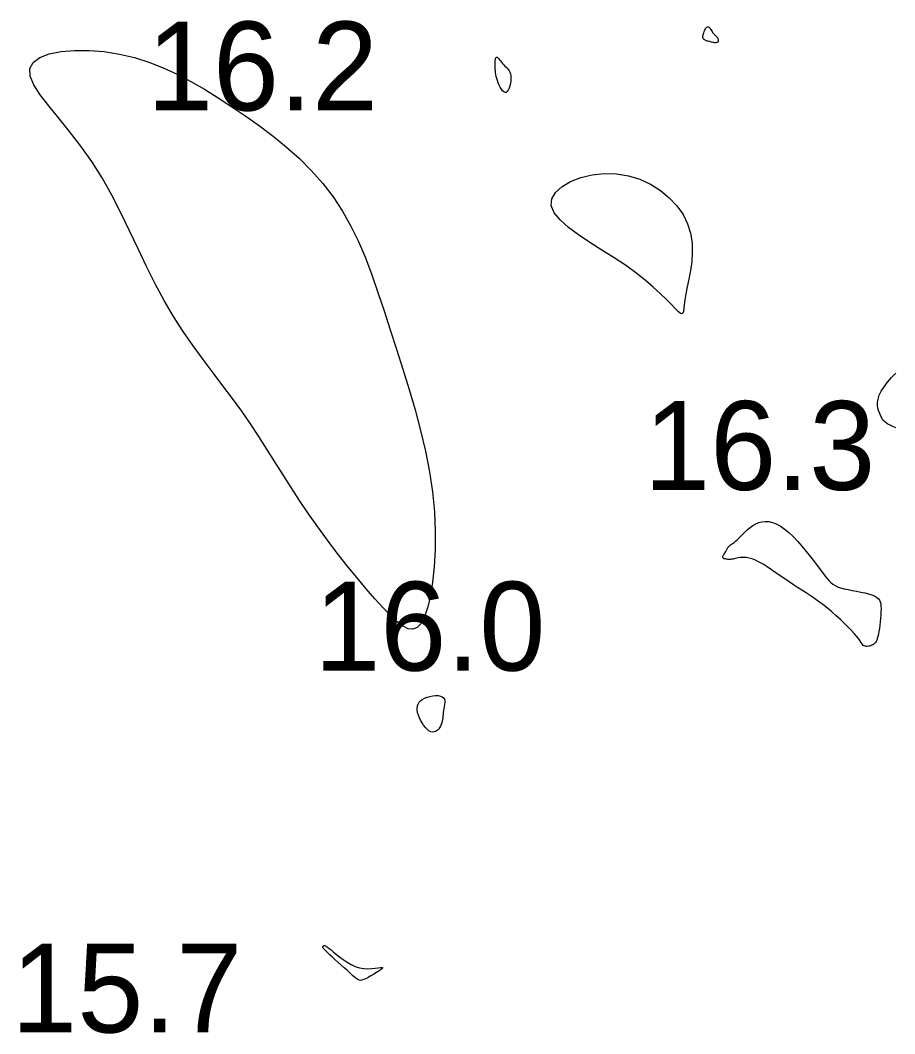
# Model space of a CAD drawing. Extents: x 3040093 to 3056816, y 408076 to 509144.
# Drawn here: x 3045855.6 to 3045904.8, y 434452.5 to 434509.6 of the extents above; entities that cross this region are included whole.
import ezdxf

# ---------------------------------------------------------------- set-up
doc = ezdxf.new("R2010")
doc.units = 0
doc.layers.add('V-CHAN-CONT-EL17', color=7, linetype='Continuous')
doc.layers.add('V-TOPO-SOUN-0610', color=7, linetype='Continuous')

msp = doc.modelspace()

# ---------------------------------------------------------------- linework, layer by layer
at = {"layer": 'V-CHAN-CONT-EL17'}
for points in [[(3045894.628, 434508.794), (3045894.661, 434508.759), (3045894.692, 434508.728), (3045894.723, 434508.701), (3045894.752, 434508.674), (3045894.779, 434508.648), (3045894.804, 434508.619), (3045894.827, 434508.588), (3045894.846, 434508.552), (3045894.861, 434508.514), (3045894.872, 434508.474), (3045894.877, 434508.435), (3045894.875, 434508.398), (3045894.866, 434508.364), (3045894.848, 434508.337), (3045894.821, 434508.316), (3045894.785, 434508.304), (3045894.739, 434508.3), (3045894.687, 434508.302), (3045894.629, 434508.309), (3045894.568, 434508.321), (3045894.504, 434508.335), (3045894.44, 434508.351), (3045894.376, 434508.367), (3045894.315, 434508.382), (3045894.257, 434508.397), (3045894.204, 434508.414), (3045894.155, 434508.433), (3045894.113, 434508.454), (3045894.076, 434508.48), (3045894.048, 434508.51), (3045894.027, 434508.547), (3045894.015, 434508.59), (3045894.011, 434508.639), (3045894.014, 434508.692), (3045894.024, 434508.749), (3045894.038, 434508.807), (3045894.057, 434508.866), (3045894.079, 434508.923), (3045894.103, 434508.979), (3045894.128, 434509.032), (3045894.154, 434509.079), (3045894.182, 434509.121), (3045894.21, 434509.155), (3045894.24, 434509.18), (3045894.27, 434509.195), (3045894.301, 434509.199), (3045894.332, 434509.19), (3045894.364, 434509.167), (3045894.396, 434509.133), (3045894.429, 434509.089), (3045894.462, 434509.04), (3045894.495, 434508.987), (3045894.528, 434508.933), (3045894.561, 434508.882), (3045894.595, 434508.834)], [(3045871.311, 434482.528), (3045870.836, 434483.26), (3045870.375, 434483.986), (3045869.922, 434484.707), (3045869.47, 434485.424), (3045869.012, 434486.137), (3045868.539, 434486.849), (3045868.047, 434487.56), (3045867.528, 434488.271), (3045866.989, 434488.989), (3045866.435, 434489.72), (3045865.873, 434490.47), (3045865.311, 434491.246), (3045864.754, 434492.053), (3045864.209, 434492.899), (3045863.684, 434493.79), (3045863.182, 434494.728), (3045862.696, 434495.705), (3045862.218, 434496.706), (3045861.738, 434497.719), (3045861.247, 434498.729), (3045860.735, 434499.725), (3045860.195, 434500.691), (3045859.616, 434501.616), (3045858.996, 434502.487), (3045858.362, 434503.301), (3045857.747, 434504.055), (3045857.184, 434504.747), (3045856.706, 434505.375), (3045856.348, 434505.936), (3045856.142, 434506.427), (3045856.121, 434506.848), (3045856.309, 434507.195), (3045856.685, 434507.47), (3045857.218, 434507.674), (3045857.878, 434507.808), (3045858.634, 434507.872), (3045859.455, 434507.869), (3045860.311, 434507.798), (3045861.171, 434507.663), (3045862.01, 434507.463), (3045862.826, 434507.204), (3045863.624, 434506.891), (3045864.408, 434506.529), (3045865.183, 434506.123), (3045865.953, 434505.68), (3045866.723, 434505.202), (3045867.497, 434504.698), (3045868.276, 434504.169), (3045869.055, 434503.614), (3045869.825, 434503.033), (3045870.575, 434502.421), (3045871.298, 434501.776), (3045871.983, 434501.097), (3045872.623, 434500.38), (3045873.207, 434499.623), (3045873.73, 434498.824), (3045874.199, 434497.984), (3045874.622, 434497.104), (3045875.011, 434496.185), (3045875.374, 434495.228), (3045875.722, 434494.235), (3045876.063, 434493.207), (3045876.408, 434492.144), (3045876.764, 434491.05), (3045877.122, 434489.929), (3045877.474, 434488.788), (3045877.81, 434487.634), (3045878.12, 434486.473), (3045878.393, 434485.312), (3045878.62, 434484.156), (3045878.791, 434483.014), (3045878.899, 434481.892), (3045878.948, 434480.806), (3045878.943, 434479.772), (3045878.891, 434478.808), (3045878.798, 434477.93), (3045878.671, 434477.154), (3045878.515, 434476.498), (3045878.338, 434475.978), (3045878.144, 434475.607), (3045877.93, 434475.379), (3045877.692, 434475.285), (3045877.427, 434475.315), (3045877.131, 434475.459), (3045876.799, 434475.709), (3045876.428, 434476.054), (3045876.013, 434476.484), (3045875.553, 434476.991), (3045875.055, 434477.564), (3045874.529, 434478.192), (3045873.984, 434478.864), (3045873.43, 434479.57), (3045872.877, 434480.3), (3045872.333, 434481.043), (3045871.809, 434481.789)], [(3045882.408, 434506.287), (3045882.379, 434506.402), (3045882.356, 434506.511), (3045882.34, 434506.616), (3045882.328, 434506.718), (3045882.321, 434506.816), (3045882.318, 434506.912), (3045882.316, 434507.007), (3045882.316, 434507.101), (3045882.317, 434507.19), (3045882.321, 434507.273), (3045882.328, 434507.347), (3045882.339, 434507.409), (3045882.354, 434507.457), (3045882.375, 434507.486), (3045882.401, 434507.495), (3045882.434, 434507.482), (3045882.473, 434507.45), (3045882.517, 434507.401), (3045882.566, 434507.341), (3045882.619, 434507.272), (3045882.676, 434507.198), (3045882.737, 434507.124), (3045882.8, 434507.052), (3045882.865, 434506.986), (3045882.93, 434506.923), (3045882.992, 434506.86), (3045883.051, 434506.793), (3045883.103, 434506.72), (3045883.147, 434506.637), (3045883.18, 434506.542), (3045883.2, 434506.43), (3045883.205, 434506.3), (3045883.198, 434506.158), (3045883.177, 434506.013), (3045883.146, 434505.872), (3045883.106, 434505.743), (3045883.057, 434505.634), (3045883.002, 434505.552), (3045882.941, 434505.507), (3045882.876, 434505.502), (3045882.808, 434505.535), (3045882.74, 434505.599), (3045882.673, 434505.688), (3045882.608, 434505.796), (3045882.548, 434505.916), (3045882.493, 434506.041), (3045882.447, 434506.167)], [(3045889.01, 434496.199), (3045888.332, 434496.629), (3045887.655, 434497.058), (3045887.013, 434497.485), (3045886.44, 434497.908), (3045885.971, 434498.325), (3045885.638, 434498.733), (3045885.478, 434499.131), (3045885.512, 434499.515), (3045885.724, 434499.876), (3045886.086, 434500.202), (3045886.568, 434500.483), (3045887.145, 434500.707), (3045887.786, 434500.863), (3045888.464, 434500.94), (3045889.152, 434500.927), (3045889.823, 434500.817), (3045890.465, 434500.616), (3045891.068, 434500.336), (3045891.622, 434499.987), (3045892.118, 434499.579), (3045892.545, 434499.124), (3045892.893, 434498.632), (3045893.152, 434498.114), (3045893.317, 434497.581), (3045893.4, 434497.041), (3045893.415, 434496.504), (3045893.381, 434495.978), (3045893.311, 434495.472), (3045893.223, 434494.996), (3045893.132, 434494.558), (3045893.054, 434494.166), (3045893.001, 434493.83), (3045892.967, 434493.552), (3045892.942, 434493.332), (3045892.917, 434493.173), (3045892.882, 434493.077), (3045892.827, 434493.045), (3045892.741, 434493.079), (3045892.617, 434493.18), (3045892.443, 434493.348), (3045892.218, 434493.577), (3045891.939, 434493.858), (3045891.604, 434494.184), (3045891.21, 434494.547), (3045890.755, 434494.938), (3045890.238, 434495.348), (3045889.655, 434495.771)], [(3045903.044, 434474.38), (3045903.002, 434474.424), (3045902.959, 434474.483), (3045902.908, 434474.557), (3045902.846, 434474.648), (3045902.766, 434474.758), (3045902.665, 434474.888), (3045902.537, 434475.04), (3045902.378, 434475.215), (3045902.192, 434475.407), (3045901.984, 434475.613), (3045901.759, 434475.828), (3045901.52, 434476.046), (3045901.273, 434476.262), (3045901.022, 434476.473), (3045900.773, 434476.671), (3045900.529, 434476.855), (3045900.289, 434477.025), (3045900.053, 434477.186), (3045899.818, 434477.34), (3045899.583, 434477.49), (3045899.348, 434477.641), (3045899.109, 434477.795), (3045898.867, 434477.955), (3045898.619, 434478.124), (3045898.369, 434478.298), (3045898.12, 434478.471), (3045897.874, 434478.64), (3045897.634, 434478.8), (3045897.403, 434478.945), (3045897.184, 434479.07), (3045896.981, 434479.172), (3045896.795, 434479.246), (3045896.626, 434479.294), (3045896.473, 434479.322), (3045896.335, 434479.333), (3045896.212, 434479.33), (3045896.103, 434479.318), (3045896.006, 434479.301), (3045895.921, 434479.282), (3045895.847, 434479.265), (3045895.781, 434479.251), (3045895.723, 434479.24), (3045895.67, 434479.231), (3045895.621, 434479.224), (3045895.574, 434479.22), (3045895.526, 434479.218), (3045895.476, 434479.218), (3045895.424, 434479.22), (3045895.369, 434479.225), (3045895.316, 434479.232), (3045895.265, 434479.243), (3045895.219, 434479.257), (3045895.181, 434479.276), (3045895.152, 434479.298), (3045895.135, 434479.326), (3045895.131, 434479.358), (3045895.139, 434479.394), (3045895.157, 434479.434), (3045895.181, 434479.477), (3045895.209, 434479.521), (3045895.24, 434479.566), (3045895.271, 434479.611), (3045895.299, 434479.656), (3045895.324, 434479.699), (3045895.344, 434479.74), (3045895.363, 434479.78), (3045895.382, 434479.819), (3045895.402, 434479.857), (3045895.425, 434479.894), (3045895.452, 434479.929), (3045895.485, 434479.964), (3045895.525, 434479.999), (3045895.573, 434480.035), (3045895.628, 434480.075), (3045895.692, 434480.121), (3045895.765, 434480.175), (3045895.846, 434480.24), (3045895.936, 434480.318), (3045896.035, 434480.411), (3045896.144, 434480.519), (3045896.261, 434480.64), (3045896.389, 434480.766), (3045896.525, 434480.893), (3045896.67, 434481.015), (3045896.824, 434481.126), (3045896.986, 434481.221), (3045897.158, 434481.294), (3045897.337, 434481.341), (3045897.525, 434481.358), (3045897.722, 434481.344), (3045897.927, 434481.297), (3045898.14, 434481.217), (3045898.363, 434481.1), (3045898.594, 434480.945), (3045898.835, 434480.751), (3045899.083, 434480.517), (3045899.336, 434480.252), (3045899.588, 434479.966), (3045899.836, 434479.668), (3045900.074, 434479.369), (3045900.297, 434479.079), (3045900.502, 434478.807), (3045900.684, 434478.563), (3045900.839, 434478.356), (3045900.973, 434478.183), (3045901.094, 434478.039), (3045901.21, 434477.922), (3045901.327, 434477.825), (3045901.454, 434477.746), (3045901.598, 434477.68), (3045901.765, 434477.623), (3045901.962, 434477.57), (3045902.182, 434477.52), (3045902.417, 434477.472), (3045902.659, 434477.426), (3045902.899, 434477.378), (3045903.129, 434477.329), (3045903.34, 434477.277), (3045903.525, 434477.221), (3045903.676, 434477.16), (3045903.795, 434477.092), (3045903.886, 434477.014), (3045903.952, 434476.927), (3045903.997, 434476.826), (3045904.025, 434476.712), (3045904.039, 434476.582), (3045904.043, 434476.433), (3045904.039, 434476.267), (3045904.03, 434476.086), (3045904.015, 434475.896), (3045903.995, 434475.703), (3045903.973, 434475.512), (3045903.947, 434475.329), (3045903.919, 434475.158), (3045903.89, 434475.006), (3045903.861, 434474.876), (3045903.83, 434474.767), (3045903.797, 434474.677), (3045903.762, 434474.603), (3045903.723, 434474.543), (3045903.68, 434474.493), (3045903.633, 434474.452), (3045903.58, 434474.418), (3045903.521, 434474.387), (3045903.459, 434474.36), (3045903.393, 434474.34), (3045903.327, 434474.325), (3045903.261, 434474.318), (3045903.199, 434474.318), (3045903.141, 434474.329), (3045903.089, 434474.349)], [(3045878.589, 434469.572), (3045878.488, 434469.653), (3045878.388, 434469.757), (3045878.292, 434469.88), (3045878.202, 434470.016), (3045878.121, 434470.16), (3045878.051, 434470.308), (3045877.995, 434470.453), (3045877.954, 434470.593), (3045877.93, 434470.725), (3045877.925, 434470.85), (3045877.939, 434470.967), (3045877.974, 434471.075), (3045878.031, 434471.173), (3045878.11, 434471.262), (3045878.215, 434471.341), (3045878.343, 434471.41), (3045878.49, 434471.466), (3045878.647, 434471.509), (3045878.808, 434471.538), (3045878.966, 434471.552), (3045879.112, 434471.549), (3045879.24, 434471.528), (3045879.343, 434471.488), (3045879.414, 434471.428), (3045879.458, 434471.351), (3045879.478, 434471.26), (3045879.481, 434471.159), (3045879.47, 434471.05), (3045879.452, 434470.936), (3045879.43, 434470.821), (3045879.41, 434470.708), (3045879.395, 434470.6), (3045879.385, 434470.496), (3045879.378, 434470.396), (3045879.369, 434470.299), (3045879.359, 434470.204), (3045879.343, 434470.11), (3045879.32, 434470.017), (3045879.287, 434469.924), (3045879.243, 434469.831), (3045879.188, 434469.742), (3045879.123, 434469.661), (3045879.05, 434469.591), (3045878.968, 434469.538), (3045878.881, 434469.506), (3045878.788, 434469.498), (3045878.69, 434469.519)], [(3045874.154, 434455.927), (3045873.996, 434456.069), (3045873.825, 434456.223), (3045873.648, 434456.383), (3045873.47, 434456.544), (3045873.3, 434456.698), (3045873.143, 434456.842), (3045873.006, 434456.968), (3045872.895, 434457.073), (3045872.806, 434457.157), (3045872.739, 434457.224), (3045872.69, 434457.275), (3045872.656, 434457.314), (3045872.634, 434457.344), (3045872.622, 434457.366), (3045872.616, 434457.384), (3045872.614, 434457.4), (3045872.616, 434457.414), (3045872.62, 434457.426), (3045872.627, 434457.438), (3045872.636, 434457.448), (3045872.646, 434457.457), (3045872.658, 434457.466), (3045872.671, 434457.474), (3045872.684, 434457.48), (3045872.702, 434457.483), (3045872.727, 434457.479), (3045872.762, 434457.465), (3045872.812, 434457.436), (3045872.879, 434457.391), (3045872.967, 434457.324), (3045873.079, 434457.235), (3045873.217, 434457.119), (3045873.38, 434456.985), (3045873.563, 434456.84), (3045873.765, 434456.692), (3045873.981, 434456.549), (3045874.208, 434456.419), (3045874.442, 434456.311), (3045874.682, 434456.233), (3045874.921, 434456.189), (3045875.154, 434456.175), (3045875.374, 434456.182), (3045875.571, 434456.201), (3045875.739, 434456.224), (3045875.87, 434456.244), (3045875.956, 434456.251), (3045875.989, 434456.237), (3045875.966, 434456.196), (3045875.893, 434456.133), (3045875.782, 434456.052), (3045875.644, 434455.961), (3045875.488, 434455.866), (3045875.327, 434455.773), (3045875.171, 434455.687), (3045875.031, 434455.616), (3045874.915, 434455.564), (3045874.818, 434455.533), (3045874.736, 434455.522), (3045874.66, 434455.534), (3045874.584, 434455.567), (3045874.502, 434455.623), (3045874.407, 434455.702), (3045874.292, 434455.803)]]:
    msp.add_lwpolyline(points, close=True, dxfattribs=at)
msp.add_lwpolyline([(3045904.878, 434486.616), (3045904.702, 434486.692), (3045904.549, 434486.766), (3045904.424, 434486.837), (3045904.323, 434486.905), (3045904.243, 434486.972), (3045904.178, 434487.04), (3045904.126, 434487.112), (3045904.081, 434487.189), (3045904.039, 434487.275), (3045903.995, 434487.37), (3045903.948, 434487.477), (3045903.903, 434487.598), (3045903.866, 434487.734), (3045903.844, 434487.886), (3045903.845, 434488.056), (3045903.876, 434488.245), (3045903.944, 434488.454), (3045904.055, 434488.686), (3045904.214, 434488.937), (3045904.412, 434489.199), (3045904.639, 434489.455), (3045904.882, 434489.692)], dxfattribs=at)

# ---------------------------------------------------------------- texts
at = {"layer": 'V-TOPO-SOUN-0610'}
for s, p in [('16.2 ', (3045862.713, 434504.49)), ('16.3 ', (3045890.703, 434483.13)), ('16.0 ', (3045872.133, 434472.96)), ('15.7 ', (3045855.073, 434452.59))]:
    msp.add_text(s, height=5, dxfattribs=at).set_placement(p)

doc.saveas('drawing.dxf')
